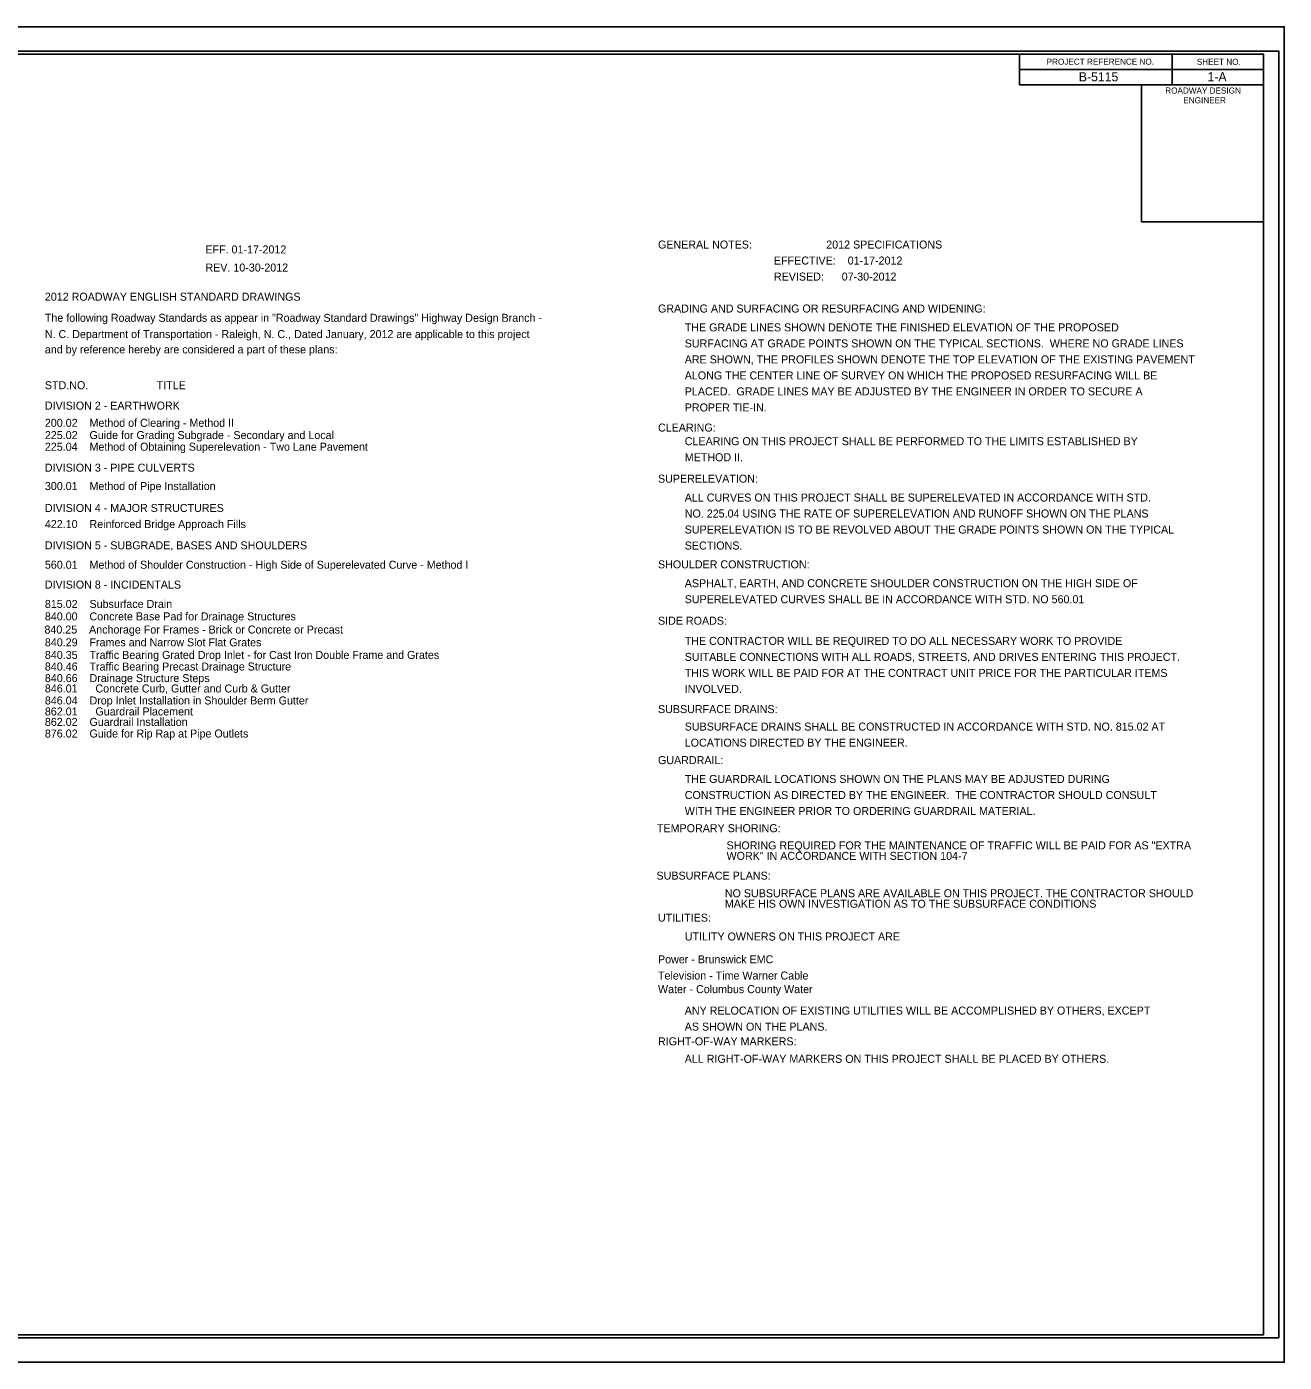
# Model space of a CAD drawing. Extents: x 1729968.4 to 1730002.1, y 539936.7 to 539958.6.
# Drawn here: x 1729981.47 to 1730002.1, y 539936.68 to 539958.58 of the extents above; entities that cross this region are included whole.
import ezdxf

# ---------------------------------------------------------------- set-up
doc = ezdxf.new("R2010")
doc.units = 0
for name, color, linetype in [('Prop RDY Alternate Text Green', 7, 'Continuous'), ('Sheet Cutting Line CELL', 7, 'Continuous'), ('Sheet Data Field CELL', 7, 'Continuous'), ('Sheet Plan CELL', 7, 'Continuous'), ('Sheet Plot Border Inside CELL', 7, 'Continuous'), ('Sheet Plot Border Outside CELL', 7, 'Continuous')]:
    doc.layers.add(name, color=color, linetype=linetype)

msp = doc.modelspace()

# ---------------------------------------------------------------- linework, layer by layer
at = {"layer": 'Sheet Cutting Line CELL'}
for p, q in [((1730002.096, 539958.582), (1729968.426, 539958.582)), ((1729968.426, 539936.682), (1730002.096, 539936.682))]:
    msp.add_line(p, q, dxfattribs=at)
at = {"layer": 'Sheet Plan CELL'}
for p, q in [((1730000.256, 539958.131), (1730000.256, 539957.631)), ((1729997.755, 539957.881), (1730001.756, 539957.881)), ((1729997.755, 539957.631), (1730001.756, 539957.631)), ((1729997.755, 539957.631), (1730001.756, 539957.631)), ((1729999.756, 539957.631), (1729999.756, 539955.382))]:
    msp.add_line(p, q, dxfattribs=at)
for points in [[(1730001.756, 539958.132), (1729971.756, 539958.132), (1729971.756, 539937.132), (1730001.756, 539937.132)], [(1729997.755, 539958.132), (1730001.756, 539958.132), (1730001.756, 539957.631), (1729997.755, 539957.631)], [(1729999.756, 539957.631), (1730001.756, 539957.631), (1730001.756, 539955.381), (1729999.756, 539955.381)]]:
    msp.add_lwpolyline(points, close=True, dxfattribs=at)
at = {"layer": 'Sheet Plot Border Inside CELL'}
msp.add_lwpolyline([(1729968.686, 539937.082), (1730002.006, 539937.082), (1730002.006, 539958.182), (1729968.686, 539958.182)], close=True, dxfattribs=at)
at = {"layer": 'Sheet Plot Border Outside CELL'}
msp.add_lwpolyline([(1729968.426, 539936.682), (1730002.096, 539936.682), (1730002.096, 539958.582), (1729968.426, 539958.582)], close=True, dxfattribs=at)

# ---------------------------------------------------------------- texts
at = {"layer": 'Prop RDY Alternate Text Green'}
for s, p in [('GENERAL NOTES:                         2012 SPECIFICATIONS', (1729991.826, 539954.944)), ('                                                      EFF. 01-17-2012', (1729981.772, 539954.864)), ('                                       EFFECTIVE:    01-17-2012', (1729991.826, 539954.682)), ('                                                      REV. 10-30-2012', (1729981.772, 539954.567)), ('                                       REVISED:      07-30-2012', (1729991.826, 539954.419)), ('2012 ROADWAY ENGLISH STANDARD DRAWINGS', (1729981.772, 539954.089)), ('GRADING AND SURFACING OR RESURFACING AND WIDENING:  ', (1729991.826, 539953.895)), ('The following Roadway Standards as appear in "Roadway Standard Drawings" Highway Design Branch -', (1729981.772, 539953.743)), ('         THE GRADE LINES SHOWN DENOTE THE FINISHED ELEVATION OF THE PROPOSED ', (1729991.826, 539953.586)), ('N. C. Department of Transportation - Raleigh, N. C., Dated January, 2012 are applicable to this project', (1729981.772, 539953.476)), ('and by reference hereby are considered a part of these plans:', (1729981.772, 539953.225)), ('         SURFACING AT GRADE POINTS SHOWN ON THE TYPICAL SECTIONS.  WHERE NO GRADE LINES ', (1729991.826, 539953.323)), ('         ARE SHOWN, THE PROFILES SHOWN DENOTE THE TOP ELEVATION OF THE EXISTING PAVEMENT ', (1729991.826, 539953.061)), ('         ALONG THE CENTER LINE OF SURVEY ON WHICH THE PROPOSED RESURFACING WILL BE ', (1729991.826, 539952.798)), ('STD.NO.                       TITLE', (1729981.772, 539952.638)), ('         PLACED.  GRADE LINES MAY BE ADJUSTED BY THE ENGINEER IN ORDER TO SECURE A ', (1729991.826, 539952.536)), ('DIVISION 2 - EARTHWORK', (1729981.772, 539952.303)), ('         PROPER TIE-IN.  ', (1729991.826, 539952.273)), ('200.02    Method of Clearing - Method II', (1729981.772, 539952.021)), ('225.02    Guide for Grading Subgrade - Secondary and Local', (1729981.772, 539951.82)), ('CLEARING:  ', (1729991.826, 539951.943)), ('225.04    Method of Obtaining Superelevation - Two Lane Pavement', (1729981.772, 539951.629)), ('         CLEARING ON THIS PROJECT SHALL BE PERFORMED TO THE LIMITS ESTABLISHED BY ', (1729991.826, 539951.72)), ('         METHOD II.', (1729991.826, 539951.457)), ('DIVISION 3 - PIPE CULVERTS', (1729981.772, 539951.286)), ('300.01    Method of Pipe Installation ', (1729981.772, 539950.984)), ('SUPERELEVATION:  ', (1729991.826, 539951.105)), ('         ALL CURVES ON THIS PROJECT SHALL BE SUPERELEVATED IN ACCORDANCE WITH STD. ', (1729991.826, 539950.796)), ('DIVISION 4 - MAJOR STRUCTURES', (1729981.772, 539950.625)), ('         NO. 225.04 USING THE RATE OF SUPERELEVATION AND RUNOFF SHOWN ON THE PLANS', (1729991.826, 539950.534)), ('422.10    Reinforced Bridge Approach Fills', (1729981.772, 539950.361)), ('         SUPERELEVATION IS TO BE REVOLVED ABOUT THE GRADE POINTS SHOWN ON THE TYPICAL ', (1729991.826, 539950.271)), ('DIVISION 5 - SUBGRADE, BASES AND SHOULDERS', (1729981.772, 539950.012)), ('         SECTIONS.  ', (1729991.826, 539950.009)), ('560.01    Method of Shoulder Construction - High Side of Superelevated Curve - Method I', (1729981.772, 539949.694)), ('SHOULDER CONSTRUCTION:  ', (1729991.826, 539949.7)), ('DIVISION 8 - INCIDENTALS', (1729981.772, 539949.368)), ('         ASPHALT, EARTH, AND CONCRETE SHOULDER CONSTRUCTION ON THE HIGH SIDE OF', (1729991.826, 539949.391)), ('815.02    Subsurface Drain', (1729981.772, 539949.051)), ('         SUPERELEVATED CURVES SHALL BE IN ACCORDANCE WITH STD. NO 560.01 ', (1729991.826, 539949.128)), ('840.00    Concrete Base Pad for Drainage Structures', (1729981.772, 539948.847)), ('SIDE ROADS:  ', (1729991.826, 539948.776)), ('840.25    Anchorage For Frames - Brick or Concrete or Precast', (1729981.765, 539948.631)), ('840.29    Frames and Narrow Slot Flat Grates', (1729981.772, 539948.422)), ('         THE CONTRACTOR WILL BE REQUIRED TO DO ALL NECESSARY WORK TO PROVIDE ', (1729991.826, 539948.445)), ('840.35    Traffic Bearing Grated Drop Inlet - for Cast Iron Double Frame and Grates', (1729981.772, 539948.215)), ('         SUITABLE CONNECTIONS WITH ALL ROADS, STREETS, AND DRIVES ENTERING THIS PROJECT.  ', (1729991.826, 539948.183)), ('840.46    Traffic Bearing Precast Drainage Structure', (1729981.772, 539948.025)), ('         THIS WORK WILL BE PAID FOR AT THE CONTRACT UNIT PRICE FOR THE PARTICULAR ITEMS ', (1729991.826, 539947.92)), ('840.66    Drainage Structure Steps', (1729981.772, 539947.835)), ('846.01      Concrete Curb, Gutter and Curb & Gutter', (1729981.772, 539947.665)), ('         INVOLVED.  ', (1729991.826, 539947.658)), ('846.04    Drop Inlet Installation in Shoulder Berm Gutter', (1729981.772, 539947.468)), ('862.01      Guardrail Placement', (1729981.772, 539947.288)), ('SUBSURFACE DRAINS:', (1729991.826, 539947.327)), ('862.02    Guardrail Installation', (1729981.772, 539947.117)), ('         SUBSURFACE DRAINS SHALL BE CONSTRUCTED IN ACCORDANCE WITH STD. NO. 815.02 AT ', (1729991.826, 539947.04)), ('876.02    Guide for Rip Rap at Pipe Outlets', (1729981.772, 539946.926)), ('         LOCATIONS DIRECTED BY THE ENGINEER.  ', (1729991.826, 539946.777)), ('GUARDRAIL:  ', (1729991.826, 539946.49)), ('         THE GUARDRAIL LOCATIONS SHOWN ON THE PLANS MAY BE ADJUSTED DURING ', (1729991.826, 539946.181)), ('         CONSTRUCTION AS DIRECTED BY THE ENGINEER.  THE CONTRACTOR SHOULD CONSULT', (1729991.826, 539945.918)), ('         WITH THE ENGINEER PRIOR TO ORDERING GUARDRAIL MATERIAL.', (1729991.826, 539945.656)), ('TEMPORARY SHORING:', (1729991.809, 539945.374)), ('SHORING REQUIRED FOR THE MAINTENANCE OF TRAFFIC WILL BE PAID FOR AS "EXTRA', (1729992.95, 539945.092)), ('WORK" IN ACCORDANCE WITH SECTION 104-7', (1729992.95, 539944.92)), ('SUBSURFACE PLANS:', (1729991.802, 539944.596)), ('NO SUBSURFACE PLANS ARE AVAILABLE ON THIS PROJECT. THE CONTRACTOR SHOULD', (1729992.922, 539944.307)), ('MAKE HIS OWN INVESTIGATION AS TO THE SUBSURFACE CONDITIONS', (1729992.922, 539944.135)), ('UTILITIES:  ', (1729991.826, 539943.907)), ('         UTILITY OWNERS ON THIS PROJECT ARE ', (1729991.826, 539943.598)), ('Power - Brunswick EMC', (1729991.826, 539943.224)), ('Television - Time Warner Cable', (1729991.826, 539942.958)), ('Water - Columbus County Water', (1729991.826, 539942.735)), ('         ANY RELOCATION OF EXISTING UTILITIES WILL BE ACCOMPLISHED BY OTHERS, EXCEPT ', (1729991.826, 539942.383)), ('         AS SHOWN ON THE PLANS.  ', (1729991.826, 539942.12)), ('RIGHT-OF-WAY MARKERS:  ', (1729991.826, 539941.879)), ('         ALL RIGHT-OF-WAY MARKERS ON THIS PROJECT SHALL BE PLACED BY OTHERS.  ', (1729991.826, 539941.592))]:
    msp.add_text(s, height=0.13122, dxfattribs=at).set_placement(p)
at = {"layer": 'Sheet Data Field CELL'}
for s, p in [('B-5115', (1729998.727, 539957.686)), ('1-A', (1730000.838, 539957.687))]:
    msp.add_text(s, height=0.15, dxfattribs=at).set_placement(p)
at = {"layer": 'Sheet Plan CELL'}
for s, p in [('PROJECT REFERENCE NO.', (1729998.199, 539957.958)), ('SHEET NO.', (1730000.662, 539957.956)), ('ROADWAY DESIGN', (1730000.144, 539957.485)), ('ENGINEER', (1730000.441, 539957.326))]:
    msp.add_text(s, height=0.1, dxfattribs=at).set_placement(p)

doc.saveas('drawing.dxf')
